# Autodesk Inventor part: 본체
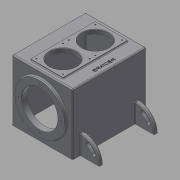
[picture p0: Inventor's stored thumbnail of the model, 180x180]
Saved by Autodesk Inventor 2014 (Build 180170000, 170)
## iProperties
Created: 2016-11
Part Number: 본체
Material: 알루미늄 6061
Document SubType Name: Modeling
Designer: mduedu
Density: 1 g/cm^3
Appearance: 기본값
Author: mduedu
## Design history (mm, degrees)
sketch "스케치1"
  geometry: L1 (-80, 0)-(80, 0); L2 (80, 0)-(80, 160); L3 (80, 160)-(-80, 160); L4 (-80, 160)-(-80, 0); 2 further points
  constraints: 8 end point, 2 parallel, 1 coincident, 1 horizontal, 1 midpoint, 1 perpendicular
  dimensions: "d0" = 160 distance of L2.end L3.end; "d2" = 160 distance of L1.end L2.end
extrude "돌출1" new body sketch "스케치1" stored distance "d3" = 194; taper "d4" = 0 deg
sketch "스케치4"
  geometry: L1 (80, 160)-(-80, 160) reference; L2 (-80, 160)-(-80, 0) reference; L3 (80, 0)-(80, 160) reference; L4 (-72, 0)-(-72, 152); L5 (-72, 152)-(72, 152); L6 (72, 152)-(72, 0); L7 (-72, 0)-(72, 0); 4 further points
  constraints: 8 end point, 1 coincident, 1 midpoint, 1 perpendicular
  dimensions: "d23" = 8 distance between parallel lines of L5 L1; "d24" = 8 distance between parallel lines of L3 L6 (= d23); "d25" = 8 distance between parallel lines of L2 L4 (= d23)
extrude "돌출4" cut sketch "스케치4" stored distance "d26" = 178; taper "d27" = 0 deg
fillet "모깎기5" dims "d28" = 3
fillet "모깎기6" dims "d29" = 3
fillet "모깎기7" dims "d30" = 3
fillet "모깎기8" dims "d31" = 3
sketch "스케치5"
  geometry: C1 r 65 at (0, 80); 1 further point
  constraints: 1 centre point, 1 vertical alignment
  dimensions: "d32" = 130 diameter of C1; "d33" = 80 distance of C1.centre point (0, 0)
extrude "돌출5" join sketch "스케치5" distance "d34" = 7; taper "d35" = 0 deg
sketch "스케치6"
  geometry: L1 (0, -3)-(154, -3) reference; L2 (154, 191)-(0, 191) reference; C1 r 35 at (77, 51.5); C2 r 35 at (77, 136.5); 2 further points
  constraints: 2 centre point, 2 vertical alignment, 1 coincident
  dimensions: "d36" = 70 diameter of C1; "d100" = 54.5 distance from line of point (77, 51.5) L1; "d101" = 70 diameter of C2; "d102" = 54.5 distance from line of C2.centre L2
extrude "돌출6" cut sketch "스케치6" stored distance "d37" = 7; taper "d38" = 0 deg
sketch "스케치7"
  geometry: L1 (34.5, 9)-(119.5, 9); L2 (119.5, 9)-(119.5, 179); L3 (119.5, 179)-(34.5, 179); L4 (34.5, 179)-(34.5, 9); L5 (0, -3)-(154, -3) reference; L6 (154, 191)-(0, 191) reference; C1 r 35 at (77, 51.5) reference; C2 r 35 at (77, 136.5) reference; 2 further points
  constraints: 8 end point, 2 parallel, 1 horizontal, 1 midpoint, 1 perpendicular, 1 vertical alignment
  dimensions: "d95" = 170 distance of L3.end L1.start; "d97" = 85 distance of L1.start L1.end; "d98" = 12 distance between parallel lines of L1 L5; "d99" = 12 distance between parallel lines of L3 L6 (derived)
extrude "돌출7" join sketch "스케치7" distance "d41" = 3; taper "d42" = 0 deg
fillet "모깎기9" dims "d43" = 3
fillet "모깎기10" dims "d44" = 2
hole "구멍2" diameter "d47" = 95; stored, may be unused: countersink angle "d51" = 90 deg, drill point angle "d53" = 118 deg; dims "d45" = 10, "d46" = 10, "d48" = 6, "d49" = 14, "d50" = 8, "d52" = 8
chamfer "모따기1" distance "d54" = 1; stored, may be unused: second distance "d55" = 2, angle "d56" = 45 deg
sketch "스케치8"
  geometry: C1 r 65 at (0, 80) reference; C2 r 31.5 at (0, 80); 1 further point
  constraints: 1 centre point, 1 coincident
  dimensions: "d57" = 63 diameter of C2
extrude "돌출8" join sketch "스케치8" distance "d58" = 14; taper "d59" = 0 deg
hole "구멍3" diameter "d62" = 30; stored, may be unused: countersink angle "d66" = 90 deg, drill point angle "d68" = 0 deg; dims "d60" = 10, "d61" = 10, "d63" = 6, "d64" = 47, "d65" = 14, "d67" = 17
fillet "모깎기11" dims "d69" = 3
fillet "모깎기12" dims "d70" = 3
fillet "모깎기13" dims "d71" = 0.5
chamfer "모따기2" distance "d72" = 1; stored, may be unused: second distance "d73" = 2, angle "d74" = 45 deg
fillet "모깎기14" dims "d75" = 3
sketch "스케치9"
  geometry: L1 (157, 0)-(157, 188) reference; L2 (77, 94)-(157, 94); 1 further point
  constraints: 2 end point, 1 midpoint, 1 point on line, 1 other
  dimensions: "d78" = 65 distance of point (142, 94) L2.start
feature "엠보싱1" sketch "스케치9" dims "d79" = 0.5, "d80" = 0
sketch "스케치10"
  geometry: 4 further points
  constraints: 4 other
hole "구멍4" sketch "스케치10" at (0, -55), (55, 0), (-55, 0), (0, 55) diameter "d81" = 3.242; stored, may be unused: countersink angle "d85" = 90 deg, drill point angle "d87" = 120 deg; dims "d82" = 6.6, "d83" = 4, "d84" = 2, "d86" = 8.6
sketch "스케치11"
  geometry: L1 (189, 94)-(-35, 94) reference; 8 further points
  constraints: 4 symmetric about line, 4 other
hole "구멍5" sketch "스케치11" at (42, 86.5), (112, 86.5), (112, 16.5), (42, 16.5), (42, 101.5), (112, 101.5), (112, 171.5), (42, 171.5) diameter "d88" = 3.242; stored, may be unused: countersink angle "d92" = 90 deg, drill point angle "d94" = 120 deg; dims "d89" = 6.6, "d90" = 4, "d91" = 2, "d93" = 8.6
node "작업 평면1"
sketch "스케치12"
  geometry: L1 (80, 157)-(80, 0) reference; L2 (80, 50)-(80, 0); L3 (80, 0)-(130, 0); L4 (80, 0)-(123.301, 25); L5 (80, 0)-(105, 43.301); A1 r 50 centre (80, 0) between (130, 0) and (80, 50); A2 r 40 centre (80, 0) between (120, 0) and (80, 40); A3 r 5 centre (114.641, 20) between (110.311, 17.5) and (118.971, 22.5); A4 r 45 centre (80, 0) between (118.971, 22.5) and (102.5, 38.971); A5 r 35 centre (80, 0) between (110.311, 17.5) and (97.5, 30.311); A6 r 5 centre (100, 34.641) between (102.5, 38.971) and (97.5, 30.311); 1 further point
  constraints: 16 point on circle, 8 end point, 8 point on line, 6 centre point, 4 coincident, 1 collinear, 1 perpendicular, 1 vertical alignment
  dimensions: "d104" = 100 diameter of A1; "d105" = 40 radius of A2; "d106" = 30 deg angle of L3 L4; "d107" = 30 deg angle of L5 L1; "d109" = 10 diameter of A3
extrude "돌출9" join sketch "스케치12" distance "d110" = 10; taper "d111" = 0 deg
extrude "돌출10" cut sketch "스케치12" stored distance "d112" = 10; taper "d113" = 0 deg
fillet "모깎기15" dims "d114" = 2
fillet "모깎기16" dims "d115" = 2
chamfer "모따기3" distance "d116" = 1; stored, may be unused: second distance "d117" = 2, angle "d118" = 45 deg
node "솔리드1"
mirror "대칭4"
